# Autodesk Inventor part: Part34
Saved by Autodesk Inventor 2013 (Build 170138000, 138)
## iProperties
Created: 2012-07
Part Number: Part34
Material: Acetal Resin, Black
Document SubType Name: Modeling
Designer: Paul
Density: 1 g/cm^3
Author: Paul
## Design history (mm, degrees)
node "User Library-Arduino Mega.SAT1"
body "Solid1"
node "Base1"
